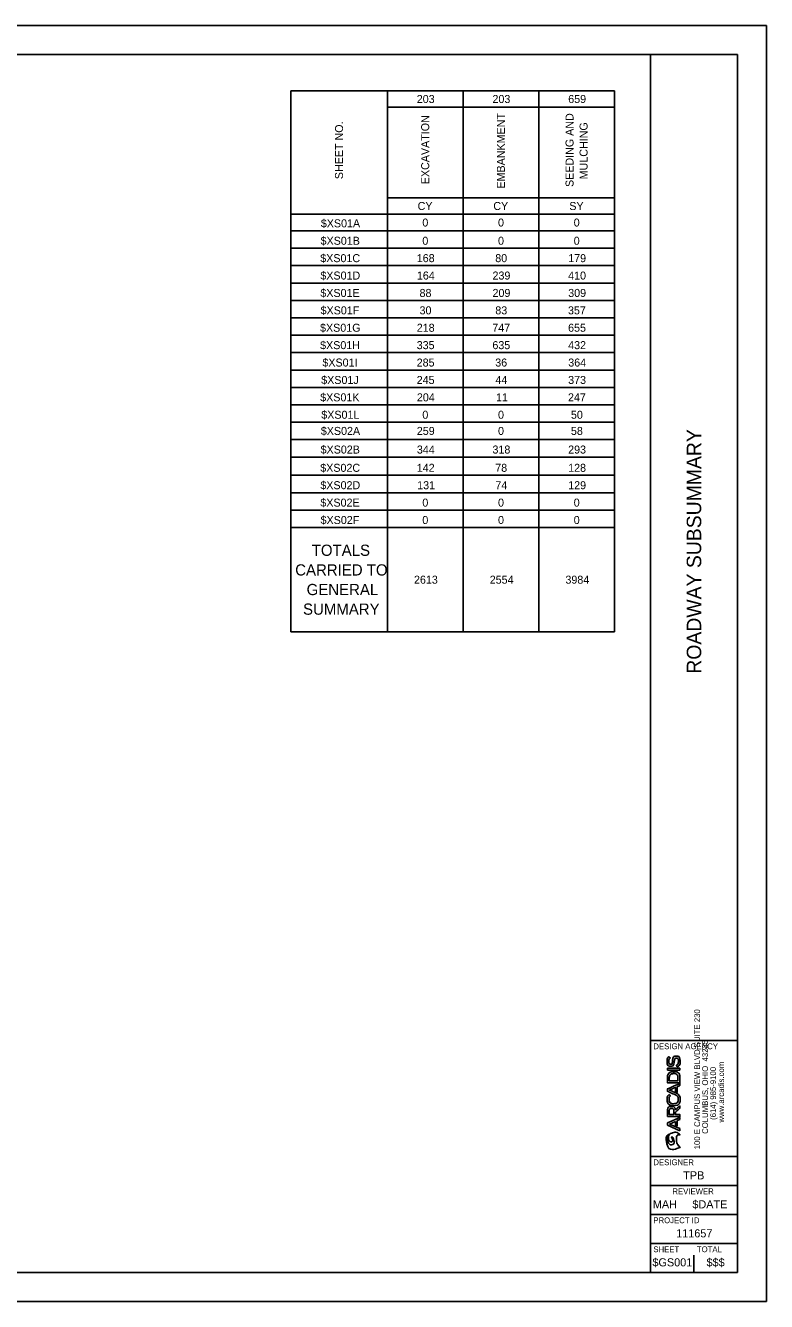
# Model space of a CAD drawing. Extents: x 0 to 34, y 0 to 22.
# Drawn here: x 21.23 to 34, y 0 to 22 of the extents above; entities that cross this region are included whole.
import ezdxf

# ---------------------------------------------------------------- set-up
doc = ezdxf.new("R2010")
doc.units = 0
for name, color, linetype in [('Default', 7, 'Continuous'), ('SH_Border', 7, 'Continuous'), ('SH_Cut_Line', 7, 'Continuous'), ('SH_Data', 7, 'Continuous')]:
    doc.layers.add(name, color=color, linetype=linetype)

msp = doc.modelspace()

# ---------------------------------------------------------------- linework, layer by layer
at = {"layer": 'Default'}
for p, q in [((25.799, 20.875), (31.379, 20.875)), ((25.799, 20.875), (25.799, 11.545)), ((27.464, 20.875), (27.464, 11.545)), ((28.769, 20.875), (28.769, 11.545)), ((30.074, 20.875), (30.074, 11.545)), ((31.379, 20.875), (31.379, 11.545)), ((27.464, 20.59), (31.379, 20.59)), ((27.464, 19.03), (31.379, 19.03)), ((25.799, 18.745), (31.379, 18.745)), ((25.799, 18.46), (31.379, 18.46)), ((25.799, 18.16), (31.379, 18.16)), ((25.799, 17.86), (31.379, 17.86)), ((25.799, 17.56), (31.379, 17.56)), ((25.799, 17.26), (31.379, 17.26)), ((25.799, 16.96), (31.379, 16.96)), ((25.799, 16.66), (31.379, 16.66)), ((25.799, 16.36), (31.379, 16.36)), ((25.799, 16.06), (31.379, 16.06)), ((25.799, 15.76), (31.379, 15.76)), ((25.799, 15.46), (31.379, 15.46)), ((25.799, 15.16), (31.379, 15.16)), ((25.799, 14.86), (31.379, 14.86)), ((25.799, 14.56), (31.379, 14.56)), ((25.799, 14.245), (31.379, 14.245)), ((25.799, 13.945), (31.379, 13.945)), ((25.799, 13.645), (31.379, 13.645)), ((25.799, 13.345), (31.379, 13.345)), ((25.799, 11.545), (31.379, 11.545))]:
    msp.add_line(p, q, dxfattribs=at)
at = {"layer": 'SH_Border'}
for p, q in [((32, 0.5), (32, 21.5)), ((32, 4.5), (33.5, 4.5)), ((32, 2.5), (33.5, 2.5)), ((32, 2), (33.5, 2)), ((32, 1.5), (33.5, 1.5)), ((32, 1), (33.5, 1))]:
    msp.add_line(p, q, dxfattribs=at)
msp.add_lwpolyline([(1.5, 21.5), (33.5, 21.5), (33.5, 0.5), (1.5, 0.5)], close=True, dxfattribs=at)
at = {"layer": 'SH_Cut_Line'}
msp.add_lwpolyline([(0, 0), (34, 0), (34, 22), (0, 22)], close=True, dxfattribs=at)
at = {"layer": 'SH_Data'}
for p, q in [((32.507, 4.022), (32.292, 4.022)), ((32.292, 4.022), (32.292, 3.988)), ((32.292, 3.988), (32.507, 3.988)), ((32.507, 3.988), (32.507, 4.022)), ((32.75, 3.5), (32.75, 3.5)), ((32.75, 3.5), (32.75, 3.5)), ((32.507, 3.175), (32.292, 3.079)), ((32.328, 3.06), (32.431, 3.105)), ((32.431, 3.105), (32.431, 3.034)), ((32.462, 3.119), (32.507, 3.139)), ((32.462, 3.02), (32.462, 3.119)), ((32.507, 3.139), (32.507, 3.175)), ((32.292, 3.079), (32.292, 3.041)), ((32.292, 3.041), (32.507, 2.945)), ((32.507, 2.981), (32.328, 3.06)), ((32.431, 3.034), (32.462, 3.02)), ((32.507, 2.945), (32.507, 2.981)), ((32.375, 0.675), (32.375, 0.675)), ((32.75, 0.5), (32.75, 0.8))]:
    msp.add_line(p, q, dxfattribs=at)
for points, degree in [([(32.34, 4.193), (32.325, 4.183), (32.316, 4.163), (32.316, 4.14), (32.316, 4.111), (32.328, 4.09), (32.348, 4.09), (32.369, 4.09), (32.375, 4.114), (32.379, 4.143), (32.385, 4.187), (32.398, 4.229), (32.446, 4.229), (32.494, 4.229), (32.512, 4.185), (32.512, 4.14), (32.512, 4.099), (32.5, 4.067), (32.463, 4.047), (32.463, 4.047), (32.446, 4.073), (32.446, 4.073), (32.472, 4.088), (32.482, 4.115), (32.482, 4.14), (32.482, 4.166), (32.473, 4.195), (32.446, 4.195), (32.422, 4.195), (32.414, 4.17), (32.41, 4.14), (32.405, 4.097), (32.394, 4.056), (32.348, 4.056), (32.303, 4.056), (32.286, 4.1), (32.286, 4.139), (32.286, 4.17), (32.293, 4.201), (32.322, 4.22), (32.322, 4.22), (32.34, 4.193), (32.34, 4.193), (32.34, 4.193), (32.34, 4.193), (32.34, 4.193)], 3), ([(32.292, 3.772), (32.292, 3.772), (32.507, 3.772), (32.507, 3.772), (32.507, 3.772), (32.507, 3.854), (32.507, 3.854), (32.507, 3.929), (32.452, 3.963), (32.398, 3.962), (32.345, 3.961), (32.292, 3.927), (32.292, 3.854)], 3), ([(32.292, 3.664), (32.292, 3.664), (32.292, 3.626), (32.292, 3.626), (32.292, 3.626), (32.432, 3.563), (32.432, 3.563), (32.432, 3.563), (32.432, 3.563), (32.432, 3.563), (32.445, 3.557), (32.453, 3.549), (32.456, 3.547), (32.471, 3.532), (32.479, 3.51), (32.479, 3.49), (32.479, 3.434), (32.44, 3.411), (32.401, 3.41), (32.361, 3.41), (32.321, 3.435), (32.321, 3.49), (32.321, 3.51), (32.328, 3.53), (32.343, 3.545), (32.343, 3.545), (32.321, 3.569), (32.321, 3.569), (32.299, 3.547), (32.288, 3.519), (32.288, 3.49), (32.288, 3.413), (32.345, 3.376), (32.401, 3.376), (32.458, 3.376), (32.512, 3.412), (32.512, 3.49), (32.512, 3.52), (32.502, 3.549), (32.48, 3.571), (32.48, 3.571), (32.466, 3.584), (32.446, 3.593), (32.446, 3.593), (32.44, 3.596), (32.44, 3.596), (32.44, 3.596), (32.425, 3.602), (32.425, 3.602), (32.425, 3.602), (32.425, 3.602), (32.425, 3.602), (32.425, 3.602), (32.328, 3.645), (32.328, 3.645), (32.328, 3.645), (32.431, 3.69), (32.431, 3.69), (32.431, 3.69), (32.431, 3.619), (32.431, 3.619), (32.431, 3.619), (32.462, 3.605), (32.462, 3.605), (32.462, 3.605), (32.462, 3.704), (32.462, 3.704), (32.462, 3.704), (32.507, 3.724), (32.507, 3.724), (32.507, 3.724), (32.507, 3.76), (32.507, 3.76), (32.507, 3.76), (32.292, 3.664), (32.292, 3.664), (32.292, 3.664), (32.292, 3.664), (32.292, 3.664)], 3), ([(32.292, 3.854), (32.292, 3.854), (32.292, 3.772), (32.292, 3.772)], 2), ([(32.474, 3.806), (32.474, 3.806), (32.325, 3.806), (32.325, 3.806)], 2), ([(32.325, 3.806), (32.325, 3.806), (32.325, 3.854), (32.325, 3.854), (32.325, 3.905), (32.361, 3.927), (32.398, 3.928), (32.435, 3.929), (32.474, 3.906), (32.474, 3.854), (32.474, 3.854), (32.474, 3.806), (32.474, 3.806)], 3), ([(32.43, 3.305), (32.423, 3.348), (32.393, 3.364), (32.362, 3.364), (32.326, 3.364), (32.292, 3.337), (32.292, 3.288), (32.292, 3.254), (32.292, 3.221), (32.292, 3.187), (32.292, 3.187), (32.507, 3.187), (32.507, 3.187), (32.507, 3.187), (32.507, 3.222), (32.507, 3.222), (32.507, 3.222), (32.433, 3.222), (32.433, 3.222), (32.433, 3.222), (32.433, 3.267), (32.433, 3.267), (32.433, 3.267), (32.507, 3.333), (32.507, 3.333), (32.507, 3.333), (32.507, 3.373), (32.507, 3.373)], 3), ([(32.323, 3.288), (32.323, 3.316), (32.344, 3.329), (32.363, 3.329), (32.383, 3.329), (32.402, 3.316), (32.402, 3.287), (32.402, 3.287), (32.402, 3.222), (32.402, 3.222), (32.402, 3.222), (32.323, 3.222), (32.323, 3.222)], 3), ([(32.507, 3.373), (32.507, 3.373), (32.43, 3.305), (32.43, 3.305)], 2), ([(32.323, 3.222), (32.323, 3.222), (32.323, 3.288), (32.323, 3.288)], 2), ([(32.272, 2.786), (32.282, 2.575), (32.514, 2.656), (32.514, 2.656), (32.494, 2.674), (32.446, 2.734), (32.446, 2.817), (32.446, 2.817), (32.446, 2.817), (32.446, 2.818), (32.446, 2.858), (32.48, 2.881), (32.514, 2.872), (32.514, 2.872), (32.441, 2.935), (32.357, 2.9), (32.329, 2.888), (32.309, 2.857), (32.309, 2.821), (32.309, 2.808), (32.311, 2.795), (32.316, 2.782), (32.329, 2.752), (32.356, 2.748), (32.369, 2.754), (32.378, 2.759), (32.383, 2.768), (32.383, 2.777), (32.383, 2.779), (32.383, 2.781), (32.383, 2.782), (32.378, 2.813), (32.364, 2.826), (32.364, 2.833), (32.364, 2.834), (32.364, 2.835), (32.365, 2.835), (32.368, 2.84), (32.383, 2.836), (32.398, 2.796), (32.402, 2.787), (32.407, 2.769), (32.407, 2.752), (32.407, 2.732), (32.401, 2.712), (32.38, 2.706), (32.343, 2.693), (32.298, 2.738), (32.293, 2.804), (32.292, 2.807), (32.292, 2.812), (32.292, 2.815), (32.292, 2.849), (32.307, 2.873), (32.317, 2.885), (32.294, 2.871), (32.273, 2.842), (32.272, 2.796), (32.272, 2.796), (32.272, 2.792), (32.272, 2.786), (32.272, 2.786), (32.272, 2.786), (32.272, 2.786)], 3)]:
    msp.add_open_spline(points, degree=degree, dxfattribs=at)

# ---------------------------------------------------------------- texts
at = {"layer": 'Default'}
for s, height, p in [('203', 0.138, (27.971, 20.664)), ('203', 0.138, (29.276, 20.664)), ('659', 0.138, (30.582, 20.664)), ('CY', 0.138, (27.986, 18.819)), ('CY', 0.138, (29.291, 18.819)), ('SY', 0.138, (30.601, 18.819)), ('$XS01A', 0.138, (26.317, 18.52)), ('0', 0.138, (28.067, 18.534)), ('0', 0.138, (29.372, 18.534)), ('0', 0.138, (30.677, 18.534)), ('$XS01B', 0.138, (26.313, 18.22)), ('0', 0.138, (28.067, 18.22)), ('0', 0.138, (29.372, 18.22)), ('0', 0.138, (30.677, 18.22)), ('$XS01C', 0.138, (26.307, 17.92)), ('168', 0.138, (27.971, 17.92)), ('80', 0.138, (29.324, 17.92)), ('179', 0.138, (30.582, 17.92)), ('$XS01D', 0.138, (26.309, 17.62)), ('164', 0.138, (27.973, 17.62)), ('239', 0.138, (29.277, 17.62)), ('410', 0.138, (30.581, 17.62)), ('$XS01E', 0.138, (26.309, 17.32)), ('88', 0.138, (28.019, 17.32)), ('209', 0.138, (29.277, 17.32)), ('309', 0.138, (30.582, 17.32)), ('$XS01F', 0.138, (26.313, 17.02)), ('30', 0.138, (28.019, 17.02)), ('83', 0.138, (29.325, 17.02)), ('357', 0.138, (30.578, 17.02)), ('$XS01G', 0.138, (26.304, 16.72)), ('218', 0.138, (27.971, 16.72)), ('747', 0.138, (29.273, 16.72)), ('655', 0.138, (30.58, 16.72)), ('$XS01H', 0.138, (26.305, 16.42)), ('335', 0.138, (27.97, 16.42)), ('635', 0.138, (29.275, 16.42)), ('432', 0.138, (30.581, 16.42)), ('$XS01I', 0.138, (26.344, 16.12)), ('285', 0.138, (27.97, 16.12)), ('36', 0.138, (29.324, 16.12)), ('364', 0.138, (30.583, 16.12)), ('$XS01J', 0.138, (26.324, 15.82)), ('245', 0.138, (27.97, 15.82)), ('44', 0.138, (29.326, 15.82)), ('373', 0.138, (30.581, 15.82)), ('$XS01K', 0.138, (26.306, 15.52)), ('204', 0.138, (27.973, 15.52)), ('11', 0.138, (29.338, 15.52)), ('247', 0.138, (30.578, 15.52)), ('$XS01L', 0.138, (26.325, 15.22)), ('0', 0.138, (28.067, 15.22)), ('0', 0.138, (29.372, 15.22)), ('50', 0.138, (30.629, 15.22)), ('$XS02A', 0.138, (26.317, 14.941)), ('259', 0.138, (27.972, 14.941)), ('0', 0.138, (29.372, 14.941)), ('58', 0.138, (30.629, 14.941)), ('$XS02B', 0.138, (26.313, 14.62)), ('344', 0.138, (27.973, 14.62)), ('318', 0.138, (29.276, 14.62)), ('293', 0.138, (30.581, 14.62)), ('$XS02C', 0.138, (26.307, 14.305)), ('142', 0.138, (27.971, 14.305)), ('78', 0.138, (29.324, 14.305)), ('128', 0.138, (30.581, 14.305)), ('$XS02D', 0.138, (26.309, 14.005)), ('131', 0.138, (27.978, 14.005)), ('74', 0.138, (29.326, 14.005)), ('129', 0.138, (30.582, 14.005)), ('$XS02E', 0.138, (26.309, 13.705)), ('0', 0.138, (28.067, 13.705)), ('0', 0.138, (29.372, 13.705)), ('0', 0.138, (30.677, 13.705)), ('$XS02F', 0.138, (26.313, 13.405)), ('0', 0.138, (28.067, 13.405)), ('0', 0.138, (29.372, 13.405)), ('0', 0.138, (30.677, 13.405)), ('TOTALS ', 0.1932, (26.16, 12.856)), ('CARRIED TO ', 0.1932, (25.875, 12.517)), ('GENERAL ', 0.1932, (26.072, 12.179)), ('2613', 0.138, (27.923, 12.376)), ('2554', 0.138, (29.229, 12.376)), ('3984', 0.138, (30.534, 12.376)), ('SUMMARY', 0.1932, (26.01, 11.841))]:
    msp.add_text(s, height=height, dxfattribs=at).set_placement(p)
for s, p in [('EMBANKMENT', (29.49, 19.189)), ('SEEDING AND ', (30.674, 19.216)), ('SHEET NO.', (26.7, 19.351)), ('EXCAVATION', (28.185, 19.264)), ('MULCHING', (30.916, 19.348))]:
    msp.add_text(s, height=0.138, rotation=90, dxfattribs=at).set_placement(p)
at = {"layer": 'SH_Data'}
for s, height, p in [('ROADWAY SUBSUMMARY', 0.25, (32.875, 10.824)), ('100 E CAMPUS VIEW BLVD SUITE 230', 0.1, (32.855, 2.623)), ('COLUMBUS, OHIO  43235', 0.1, (32.992, 2.89)), ('(614) 985-9100', 0.1, (33.13, 3.13)), ('www.arcadis.com', 0.1, (33.268, 3.085))]:
    msp.add_text(s, height=height, rotation=90, dxfattribs=at).set_placement(p)
for s, height, p in [('DESIGN AGENCY', 0.1, (32.05, 4.35)), ('DESIGNER', 0.1, (32.05, 2.35)), ('TPB', 0.14, (32.565, 2.105)), ('REVIEWER', 0.1, (32.378, 1.85)), ('MAH', 0.14, (32.041, 1.605)), ('$DATE', 0.14, (32.722, 1.605)), ('PROJECT ID', 0.1, (32.05, 1.35)), ('111657', 0.14, (32.443, 1.105)), ('SHEET', 0.1, (32.05, 0.85)), ('TOTAL', 0.1, (32.8, 0.85)), ('$GS001', 0.14, (32.034, 0.605)), ('$$$', 0.14, (32.967, 0.605))]:
    msp.add_text(s, height=height, dxfattribs=at).set_placement(p)

doc.saveas('drawing.dxf')
